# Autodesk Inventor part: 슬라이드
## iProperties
Company: 한국ATC센터
Created: 2014-10
Part Number: 슬라이드
Document SubType Name: Modeling
Designer: 한국ATC센터
Density: 7.86 g/cm^3
Material: 강, 연강
Mass: 728.405 g
Surface Area: 164.68 cm^2
Volume: 92.6724 cm^3
Author: KYOUNG IL JANG
Revision Number: 1
